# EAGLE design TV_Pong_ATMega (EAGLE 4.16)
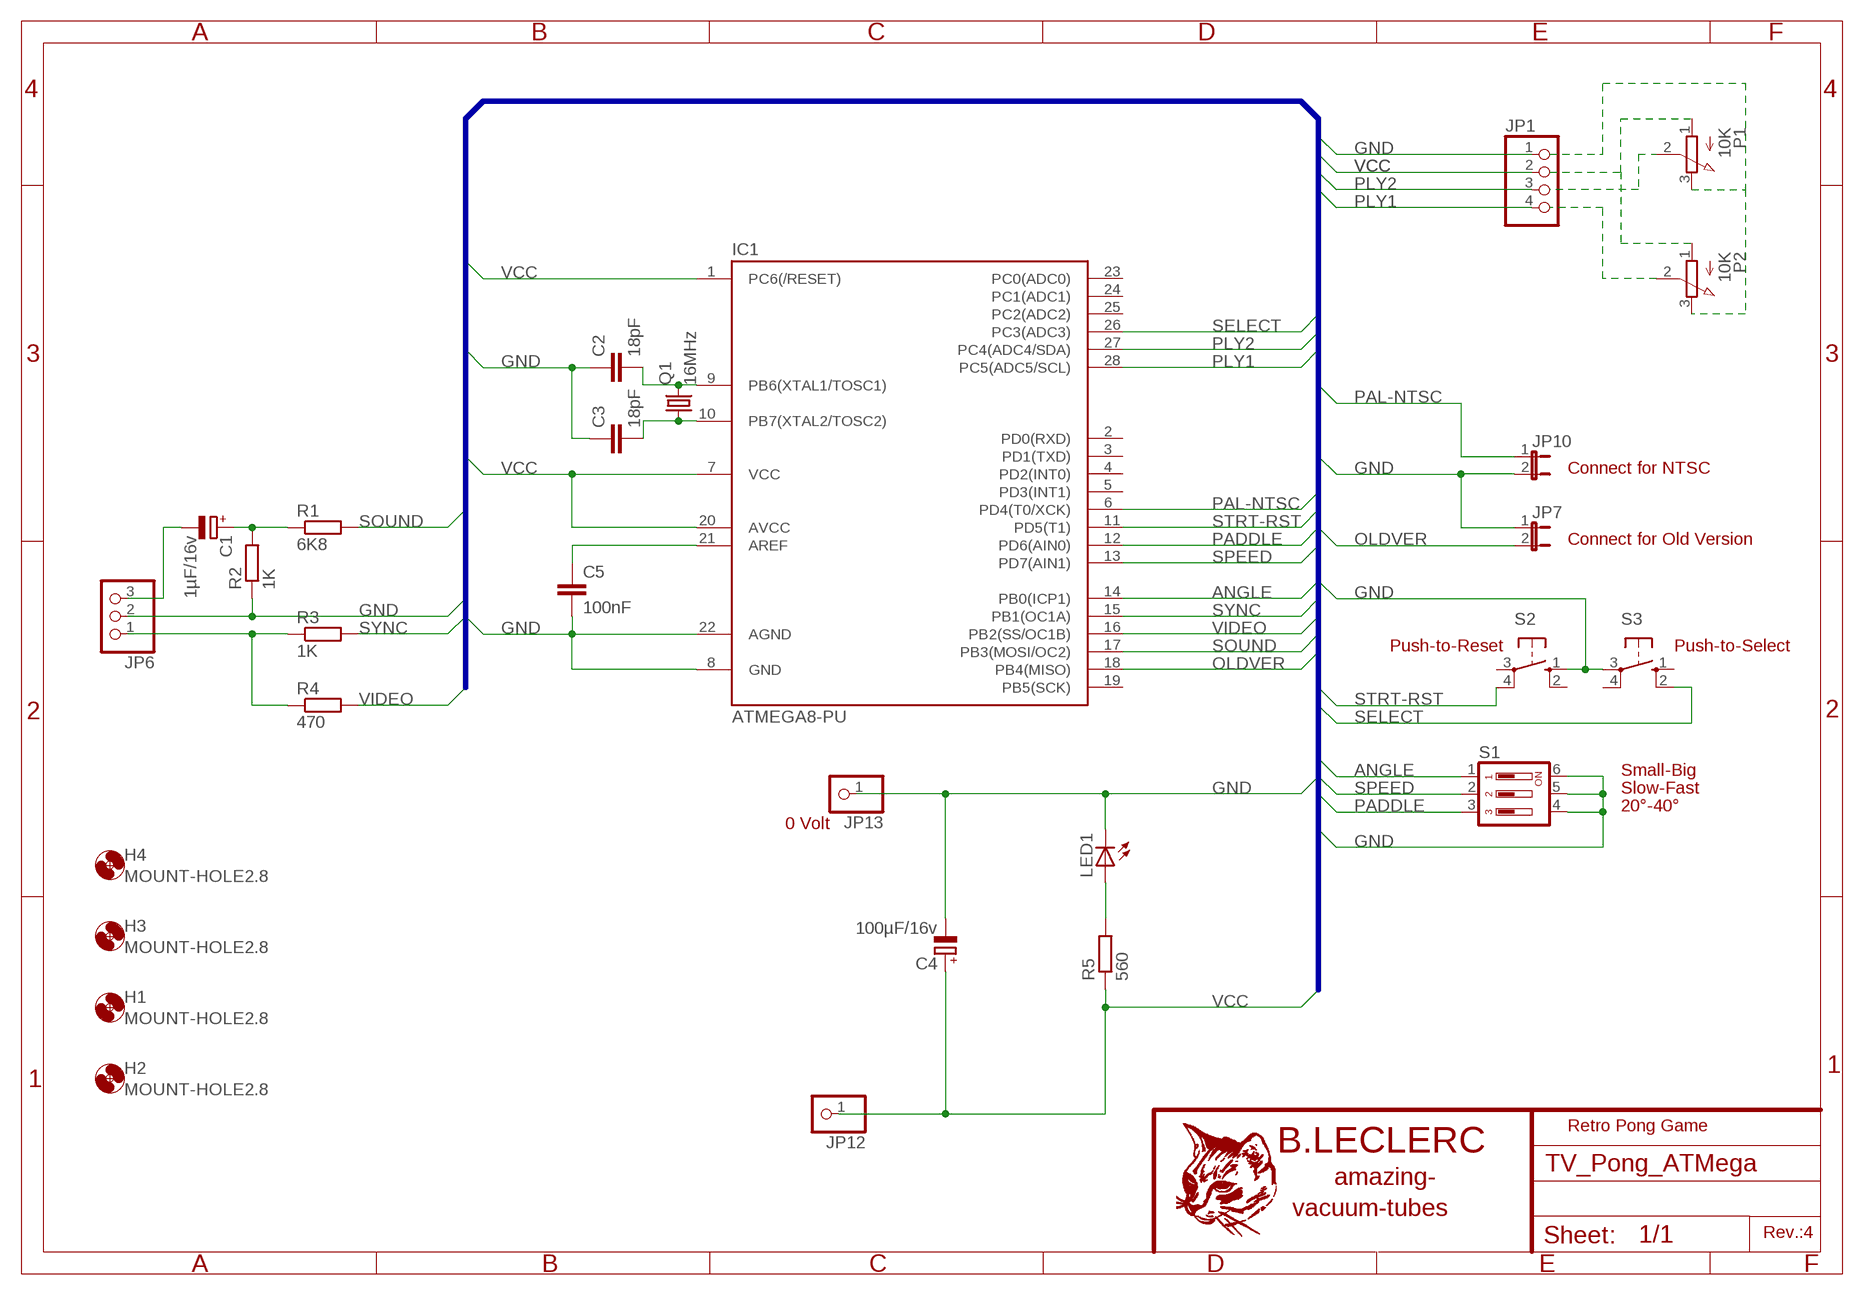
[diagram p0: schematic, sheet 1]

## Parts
C1  1µF/16v  CPOL-EU153CLV-0605  [153CLV-0605]
C2  18pF  C-EUC1206  [C1206]
C3  18pF  C-EUC1206  [C1206]
C4  100µF/16v  CPOL-EU153CLV-0605  [153CLV-0605]
C5  100nF  C-EUC1206  [C1206]
H1  MOUNT-HOLE2.8  [2,8]
H2  MOUNT-HOLE2.8  [2,8]
H3  MOUNT-HOLE2.8  [2,8]
H4  MOUNT-HOLE2.8  [2,8]
IC1  ATMEGA8-PU  [DIL28-3]
JP1  PINHD-1X4  [1X04]
JP6  PINHD-1X3  [1X03]
JP7  JP1E  [JP1]
JP10  JP1E  [JP1]
JP12  PINHD-1X1  [1X01]
JP13  PINHD-1X1  [1X01]
LED1  LED3MM  [LED3MM]
P1  10K  STD-EU  [STD-EU]
P2  10K  STD-EU  [STD-EU]
Q1  16MHz  CRYTALHC49UP  [HC49UP]
R1  6K8  R-EU_M1206  [M1206]
R2  1K  R-EU_M1206  [M1206]
R3  1K  R-EU_M1206  [M1206]
R4  470  R-EU_M1206  [M1206]
R5  560  R-EU_M1206  [M1206]
S1  DS03  [DS-03]
S2  10-XX  [B3F-10XX]
S3  10-XX  [B3F-10XX]

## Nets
ANGLE: IC1.14(PB0(ICP1)) S1.1
GND: C2.1 C3.1 C4.- C5.2 IC1.8(GND) IC1.22(AGND) JP1.1 JP6.2 JP7.1 JP10.2 JP13.1 LED1.K(C) R2.1 S1.4 S1.5 S1.6 S2.1(S) S3.3(P)
N$2: C1.+ R1.1 R2.2
N$3: C1.- JP6.3
N$4: C2.2 IC1.9(PB6(XTAL1/TOSC1)) Q1.2
N$5: C3.2 IC1.10(PB7(XTAL2/TOSC2)) Q1.1
N$6: C5.1 IC1.21(AREF)
N$7: JP6.1 R3.1 R4.1
N$8: P2.2(S)
N$9: P1.3(E) P2.3(E)
N$10: P1.1(A) P2.1(A)
N$12: P1.2(S)
N$53: LED1.A R5.2
OLDVER: IC1.18(PB4(MISO)) JP7.2
PADDLE: IC1.12(PD6(AIN0)) S1.3
PAL-NTSC: IC1.6(PD4(T0/XCK)) JP10.1
PLY1: IC1.28(PC5(ADC5/SCL)) JP1.4
PLY2: IC1.27(PC4(ADC4/SDA)) JP1.3
SELECT: IC1.26(PC3(ADC3)) S3.2(S1)
SOUND: IC1.17(PB3(MOSI/OC2)) R1.2
SPEED: IC1.13(PD7(AIN1)) S1.2
STRT-RST: IC1.11(PD5(T1)) S2.4(P1)
SYNC: IC1.15(PB1(OC1A)) R3.2
VCC: C4.+ IC1.1(PC6(/RESET)) IC1.7(VCC) IC1.20(AVCC) JP1.2 JP12.1 R5.1
VIDEO: IC1.16(PB2(SS/OC1B)) R4.2
Unconnected: IC1.2(PD0(RXD)) IC1.3(PD1(TXD)) IC1.4(PD2(INT0)) IC1.5(PD3(INT1)) IC1.19(PB5(SCK)) IC1.23(PC0(ADC0)) IC1.24(PC1(ADC1)) IC1.25(PC2(ADC2)) S2.2(S1) S2.3(P) S3.1(S) S3.4(P1)

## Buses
B$1

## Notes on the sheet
- Connect for NTSC
- Connect for Old Version
- Push-to-Reset | Push-to-Select
- Small-Big
- Slow-Fast
- 20°-40°
- 0 Volt
- Retro Pong Game
- Rev.:4

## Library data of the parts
C1 C4 = rcl:CPOL-EU: POLARIZED CAPACITOR, European symbol
C2 C3 C5 = rcl:C-EU: CAPACITOR, European symbol
H1-H4 = holes:MOUNT-HOLE: MOUNTING HOLE with drill center marker
IC1 = atmega8:ATMEGA8-PU
JP1 = pinhead:PINHD-1X4: PIN HEADER
JP6 = pinhead:PINHD-1X3: PIN HEADER
JP7 JP10 = jumper:JP1E: JUMPER
JP12 JP13 = pinhead:PINHD-1X1: PIN HEADER
LED1 = led:LED: LED
P1 P2 = pot:STD-EU
Q1 = crystal:CRYTAL: CRYSTAL
R1-R5 = rcl:R-EU_: RESISTOR, European symbol
S1 = switch-dil:DS03: DIL/CODE SWITCH
S2 S3 = switch-omron:10-XX: OMRON SWITCH

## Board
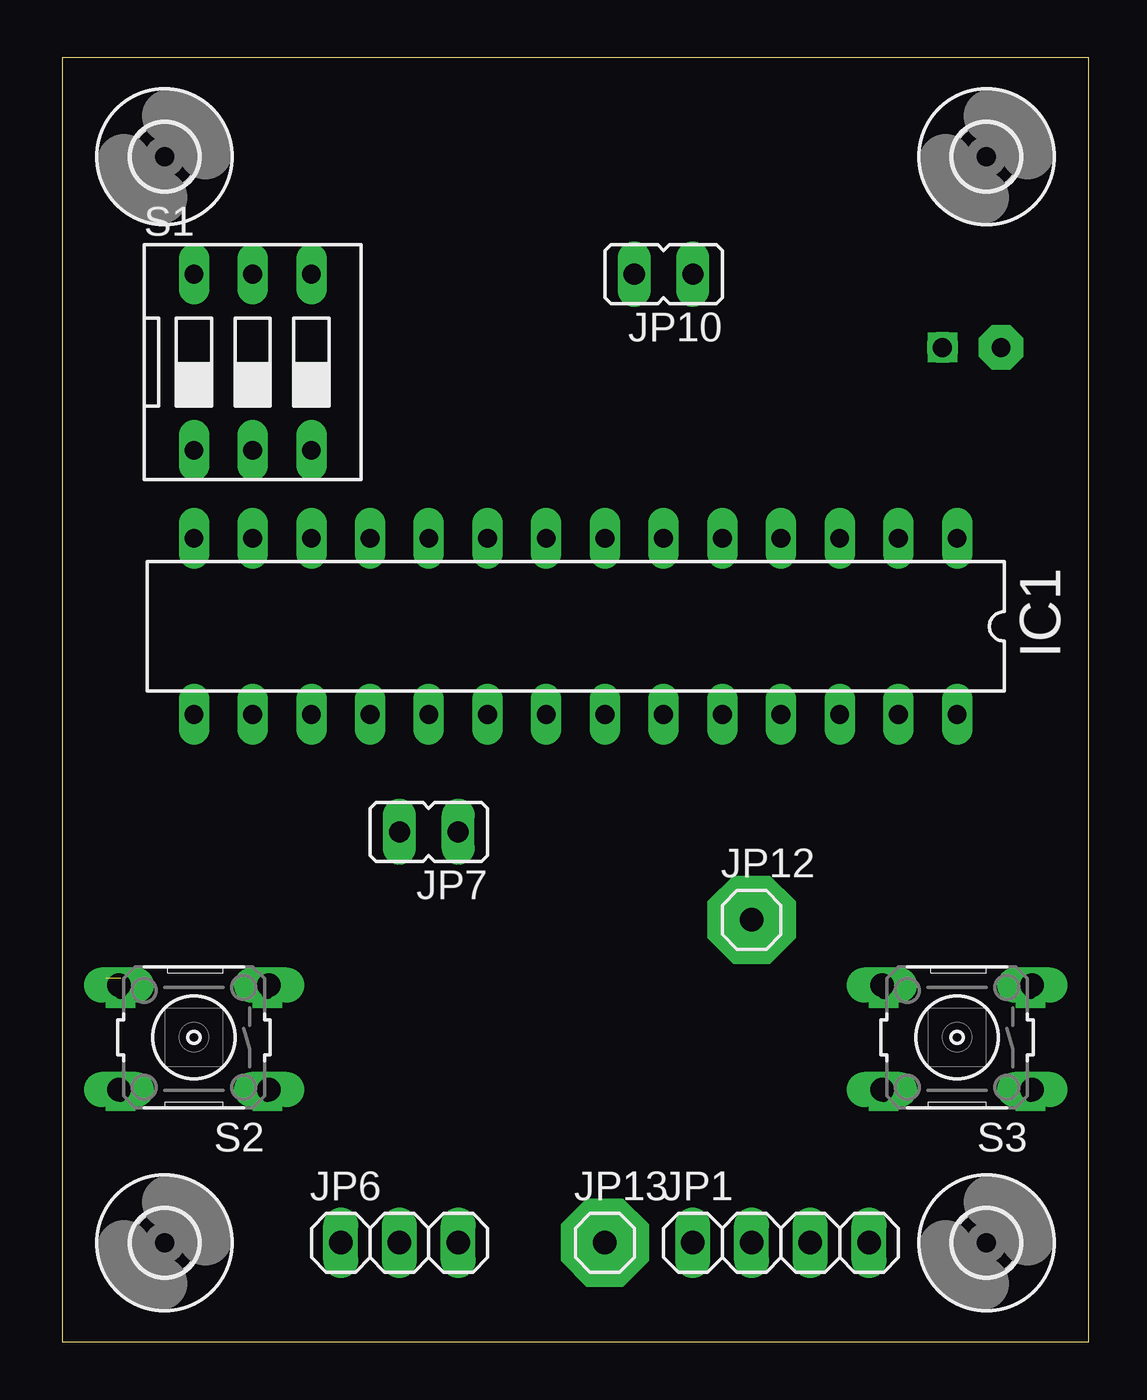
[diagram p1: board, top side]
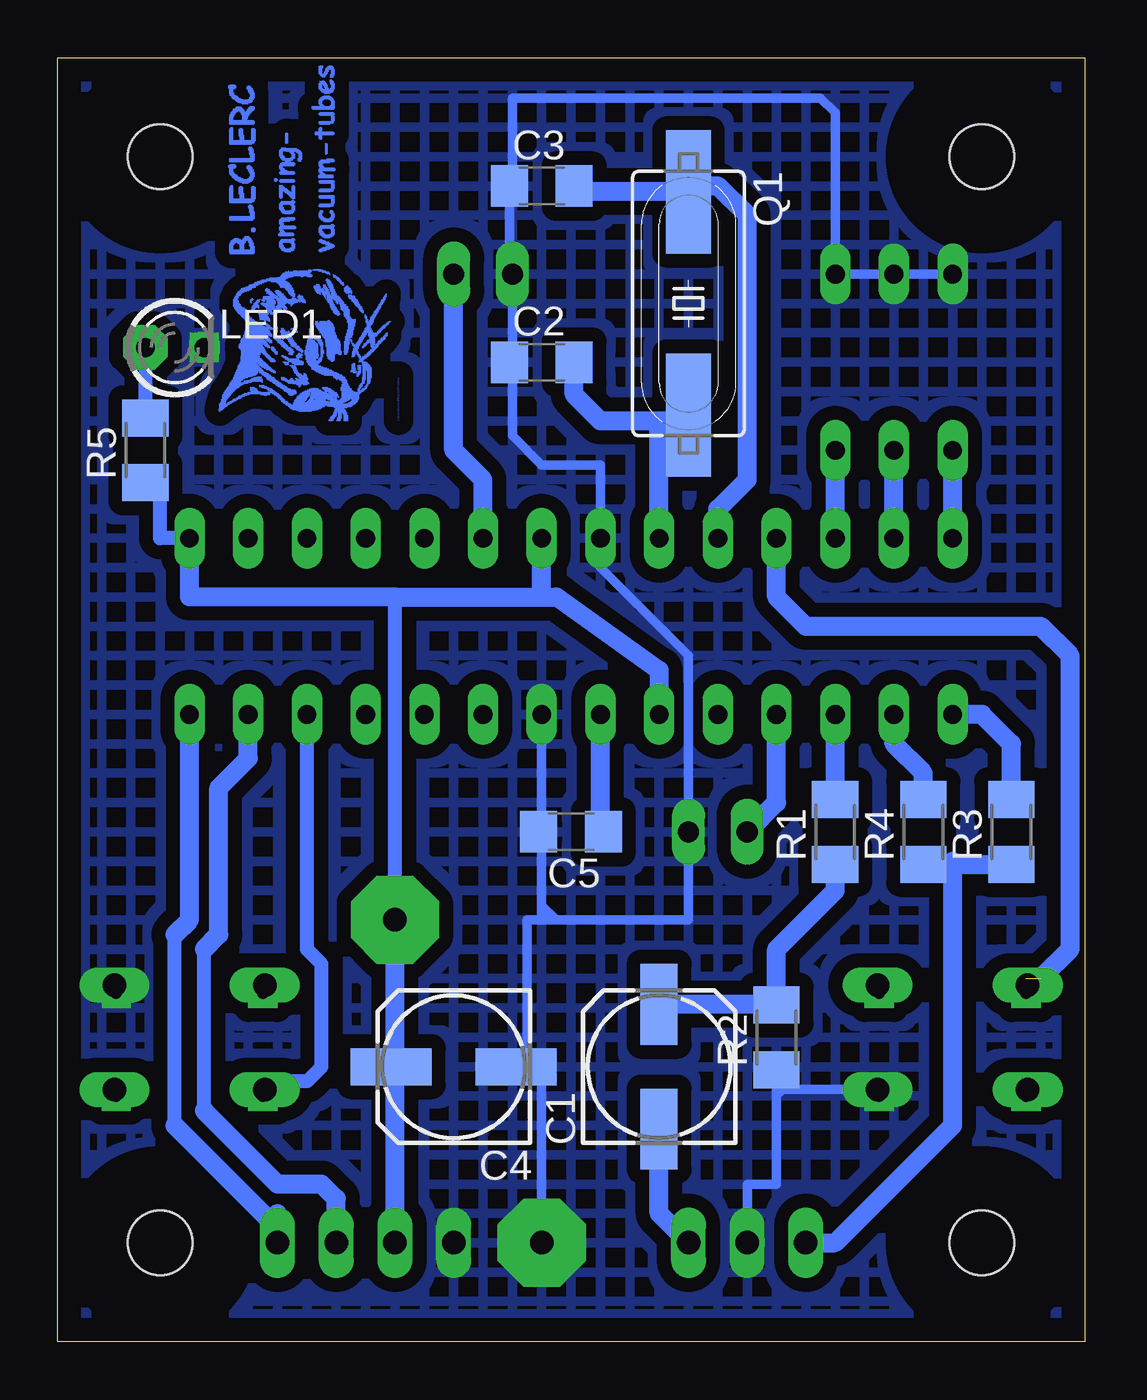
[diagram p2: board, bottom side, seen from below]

Size 44.43 x 55.55 mm. Coordinates in mm from the lower left corner, seen from the top.
Outline: 0,0 44.43,0 44.43,55.55 0,55.55 0,0
Copper layers (1*16): Top 0.035mm / dielectric 1.5mm / Bottom 0.035mm
Design rules "default": minimum track width 10mil, minimum drill 24mil, track to track 8mil, track to pad 8mil, pad to pad 8mil, via to via 8mil, smd to smd 8mil, copper to edge 40mil, drill to drill 8mil, minimum pad ring 10mil, minimum via ring 8mil, stop-mask expansion 4mil, vias tented up to drill 0mil, thermal gap 10mil

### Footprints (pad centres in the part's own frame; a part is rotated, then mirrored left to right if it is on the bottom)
153CLV-0605 = smd 3.5 x 1.6: + 2.7,0; - -2.7,0
C1206 = smd 1.6 x 1.8: 1 -1.4,0; 2 1.4,0
2,8 = hole 2.8: 0,0
DIL28-3 = drill 0.813 long: 1 -16.51,-3.81; 2 -13.97,-3.81; 3 -11.43,-3.81; 4 -8.89,-3.81; 5 -6.35,-3.81; 6 -3.81,-3.81; 7 -1.27,-3.81; 8 1.27,-3.81; 9 3.81,-3.81; 10 6.35,-3.81; 11 8.89,-3.81; 12 11.43,-3.81; 13 13.97,-3.81; 14 16.51,-3.81; 15 16.51,3.81; 16 13.97,3.81; 17 11.43,3.81; 18 8.89,3.81; 19 6.35,3.81; 20 3.81,3.81; 21 1.27,3.81; 22 -1.27,3.81; 23 -3.81,3.81; 24 -6.35,3.81; 25 -8.89,3.81; 26 -11.43,3.81; 27 -13.97,3.81; 28 -16.51,3.81
1X04 = drill 1.016 long: 1 -3.81,0; 2 -1.27,0; 3 1.27,0; 4 3.81,0
1X03 = drill 1.016 long: 1 -2.54,0; 2 0,0; 3 2.54,0
JP1 = drill 0.914 long: 1 0,-1.27; 2 0,1.27
1X01 = drill 1.016 octagon: 1 0,0
LED3MM = drill 0.813 octagon: A -1.27,0; K 1.27,0
STD-EU = drill 0.5 pad 2.184 octagon: 1 -5.08,0; 2 0,0; 3 5.08,0
HC49UP = smd 5.334 x 1.93: 1 -4.826,0; 2 4.826,0
M1206 = smd 1.6 x 2: 1 -1.4,0; 2 1.4,0
DS-03 = drill 0.813 long: 1 -2.54,-3.81; 2 0,-3.81; 3 2.54,-3.81; 4 2.54,3.81; 5 0,3.81; 6 -2.54,3.81
B3F-10XX = drill 1.016 long: 1 -3.251,2.261; 2 3.251,2.261; 3 -3.251,-2.261; 4 3.251,-2.261

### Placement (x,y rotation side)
C1  18.41,11.9 90 bottom
C2  23.49,42.38 0 bottom
C3  23.49,50 0 bottom
C4  27.3,11.9 180 bottom
C5  22.22,22.06 180 bottom
H1  40,4.28 0 top
H2  4.44,4.28 0 top
H3  4.44,51.27 0 top
H4  40,51.27 0 top
IC1  22.22,30.95 180 top
JP1  31.11,4.28 0 top
JP6  14.6,4.28 0 top
JP7  15.87,22.06 90 top
JP10  26.03,46.19 90 top
JP12  29.84,18.25 0 top
JP13  23.49,4.28 0 top
LED1  39.37,43.02 0 bottom
P1  not placed on the board
P2  not placed on the board
Q1  17.14,44.92 270 bottom
R1  10.79,22.06 90 bottom
R2  13.33,13.17 90 bottom
R3  3.17,22.06 90 bottom
R4  6.98,22.06 90 bottom
R5  40.64,38.57 90 bottom
S1  8.25,42.38 0 top
S2  5.71,13.17 180 top
S3  38.73,13.17 180 top
U$2  [CHAT]  29.84,39.84 90 bottom

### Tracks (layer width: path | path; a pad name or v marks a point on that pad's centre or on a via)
ANGLE
  Bottom 0.813: IC1.14 S1.1
GND  (via drill 0.5 pad 1.27, 0.5 pad 3.81)
  Bottom 0.406: S1.6 S1.5 S1.4 10.79,53.17 11.43,53.81 24.76,53.81 24.76,50 C3.1 24.89,46.32 JP10.2 24.76,42.38 | 24.76,42.38 C2.1 | 24.76,42.38 24.76,39.2 23.49,37.94 20.95,37.94 IC1.8 20.95,33.49 17.14,29.68 JP7.1 17.14,18.25 22.86,18.25 | 23.49,22.06 IC1.22 | 22.86,18.25 23.49,18.88 | 23.49,18.88 23.49,18.25 | 23.49,22.06 C5.2 | 23.49,18.88 23.49,22.06 | 24.12,11.9 C4.- | JP13.1 23.49,11.27 24.12,11.9 | 24.12,11.9 24.12,18.25 22.86,18.25 | S2.1 13.05,10.91 13.33,10.63 R2.1 | R2.1 13.33,11.9 | R2.1 13.33,6.82 14.6,6.82 JP6.2
  other vias: 23.49,4.28 5.71,46.19 8.25,46.19 10.79,46.19 24.76,46.19 17.14,22.06 8.89,10.63 41.91,15.08 14.6,4.28 27.3,4.28 20.95,34.76 23.49,27.14 38.1,43.02
  pour Bottom (isolate 0.61, no thermals, hatched): 0.63,55.08 43.81,55.08 44.45,54.45 44.45,1.1 43.81,0.47 0.63,0.47
N$1  (via drill 0.5 pad 1.27)
  other vias: 5.71,34.76
N$2
  Bottom 0.813: R1.1 10.79,19.52 13.33,16.98 R2.2 13.33,14.44 13.49,14.6 C1.+
N$3
  Bottom 0.813: C1.- 18.41,5.55 JP6.3
N$4
  Bottom 0.813: IC1.9 18.41,39.84 17.14,39.84 | C2.2 22.09,40.98 20.95,39.84 17.14,39.84 | 17.14,39.84 Q1.2
N$5
  Bottom 0.813: IC1.10 15.87,36.03 14.6,37.3 14.6,48.73 15.87,50 17.14,50 Q1.1 21.97,49.75 22.22,50 C3.2
N$6
  Bottom 0.813: C5.1 20.95,22.06 IC1.21
N$7
  Bottom 0.813: R4.1 6.98,20.79 6.85,20.66 5.71,20.66 | 5.71,20.66 R3.1 | JP6.1 10.79,4.28 5.71,9.36 5.71,20.66 | 5.71,20.66 5.71,20.79
N$9  (1 unrouted)
N$10  (1 unrouted)
N$11  (via drill 0.5 pad 1.27)
  other vias: 8.25,34.76
N$13  (via drill 0.5 pad 1.27)
  other vias: 13.33,34.76
N$14  (via drill 0.5 pad 1.27)
  other vias: 5.71,38.57
N$15  (via drill 0.5 pad 1.27)
  other vias: 8.25,38.57
N$16  (via drill 0.5 pad 1.27)
  other vias: 10.79,38.57
N$17  (via drill 0.5 pad 1.27)
  other vias: 15.87,34.76
N$18  (via drill 0.5 pad 1.27)
  other vias: 27.3,46.19
N$19  (via drill 0.5 pad 1.27)
  other vias: 2.54,15.08
N$20  (via drill 0.5 pad 1.27)
  other vias: 8.89,15.08
N$21  (via drill 0.5 pad 1.27)
  other vias: 2.54,10.63
N$22  (via drill 0.5 pad 1.27)
  other vias: 18.41,34.76
N$23  (via drill 0.5 pad 1.27)
  other vias: 35.55,15.08
N$24  (via drill 0.5 pad 1.27)
  other vias: 5.71,27.14
N$25  (via drill 0.5 pad 1.27)
  other vias: 35.55,10.63
N$26  (via drill 0.5 pad 1.27)
  other vias: 41.91,10.63
N$27  (via drill 0.5 pad 1.27)
  other vias: 23.49,34.76
N$28  (via drill 0.5 pad 1.27)
  other vias: 14.6,22.06
N$29  (via drill 0.5 pad 1.27)
  other vias: 12.06,4.28
N$30  (via drill 0.5 pad 1.27)
  other vias: 26.03,34.76
N$31  (via drill 0.5 pad 1.27)
  other vias: 17.14,4.28
N$32  (via drill 0.5 pad 1.27)
  other vias: 28.57,34.76
N$33  (via drill 0.5 pad 1.27)
  other vias: 29.84,4.28
N$34  (via drill 0.5 pad 1.27)
  other vias: 32.38,4.28
N$35  (via drill 0.5 pad 1.27)
  other vias: 34.92,4.28
N$36  (via drill 0.5 pad 1.27)
  other vias: 31.11,34.76
N$37  (via drill 0.5 pad 1.27)
  other vias: 33.65,34.76
N$38  (via drill 0.5 pad 1.27)
  other vias: 36.19,34.76
N$39  (via drill 0.5 pad 1.27)
  other vias: 38.73,34.76
N$40  (via drill 0.5 pad 1.27)
  other vias: 8.25,27.14
N$41  (via drill 0.5 pad 1.27)
  other vias: 13.33,27.14
N$42  (via drill 0.5 pad 1.27)
  other vias: 10.79,27.14
N$43  (via drill 0.5 pad 1.27)
  other vias: 18.41,27.14
N$44  (via drill 0.5 pad 1.27)
  other vias: 15.87,27.14
N$45  (via drill 0.5 pad 1.27)
  other vias: 28.57,27.14
N$46  (via drill 0.5 pad 1.27)
  other vias: 26.03,27.14
N$47  (via drill 0.5 pad 1.27)
  other vias: 20.95,27.14
N$48  (via drill 0.5 pad 1.27)
  other vias: 38.73,27.14
N$49  (via drill 0.5 pad 1.27)
  other vias: 36.19,27.14
N$50  (via drill 0.5 pad 1.27)
  other vias: 31.11,27.14
N$51  (via drill 0.5 pad 1.27)
  other vias: 33.65,27.14
N$52  (via drill 0.5 pad 1.27)
  other vias: 10.79,34.76
N$53
  Bottom 0.61: R5.2 LED1.A
N$54  (via drill 0.5 pad 1.93)
  other vias: 40.64,43.02
OLDVER
  Bottom 0.813: IC1.18 13.33,23.33 JP7.2
PADDLE
  Bottom 0.813: IC1.12 S1.3
PAL-NTSC
  Bottom 0.813: JP10.1 27.3,38.57 26.03,37.3 IC1.6
PLY1
  Bottom 0.61: 39.37,9.36 39.37,17.61
  Bottom 0.813: JP1.4 34.92,4.92 | 34.92,4.92 34.92,5.55 | IC1.28 38.73,18.25 39.37,17.61 | 34.92,4.92 39.37,9.36
PLY2
  Bottom 0.61: 38.1,10 38.1,16.98
  Bottom 0.813: 32.38,5.55 JP1.3 32.38,6.18 33.02,6.82 34.92,6.82 38.1,10 | IC1.27 36.19,25.23 37.46,23.96 37.46,17.61 38.1,16.98
SELECT
  Bottom 0.61: IC1.26 33.65,16.98 33.02,16.34 33.02,11.9 33.65,11.27 34.92,11.27 35.48,10.71 | 35.48,10.71 35.55,10.63 | 35.48,10.71 S3.2
SOUND
  Bottom 0.813: 10.79,23.33 R1.2 IC1.17
SPEED
  Bottom 0.813: IC1.13 S1.2
STRT-RST  (1 unrouted)
  Bottom 0.61: S2.4 2.54,15.43 | 2.54,15.43 2.54,15.71 | 2.54,15.43 2.54,15.08
  Bottom 0.813: IC1.11 13.33,32.22 12.06,30.95 1.9,30.95 0.63,29.68 0.63,16.98 1.9,15.71
SYNC
  Bottom 0.813: IC1.15 4.44,27.14 3.17,25.87 R3.2 3.17,23.33
VCC  (via drill 0.5 pad 3.81)
  Bottom 0.61: JP12.1 29.84,32.22 | R5.1 40,37.17 40,34.76 IC1.1
  Bottom 0.813: IC1.1 38.73,32.22 29.84,32.22 23.49,32.22 | 23.49,32.22 IC1.7 | 23.49,32.22 22.86,32.22 18.41,29.04 IC1.20 | 29.84,11.9 JP12.1 | 29.84,11.9 C4.+ | JP1.2 29.84,11.9
  other vias: 29.84,18.25
VIDEO
  Bottom 0.813: IC1.16 8.25,25.87 6.98,24.6 R4.2 6.98,23.33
